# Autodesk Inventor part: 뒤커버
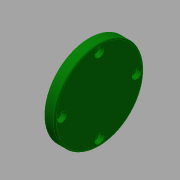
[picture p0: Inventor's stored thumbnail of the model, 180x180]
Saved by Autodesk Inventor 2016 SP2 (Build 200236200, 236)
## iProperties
Created: 2015-09
Part Number: 뒤커버
Material: 알루미늄 6061
Document SubType Name: Modeling
Designer: mduedu
Density: 2.71 g/cm^3
Mass: 54.0417 g
Surface Area: 84.9688 cm^2
Volume: 19.9416 cm^3
Appearance: 진녹색
Author: mduedu
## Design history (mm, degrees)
sketch "스케치1"
  geometry: L1 (-15.5, 47)-(-15.5, 78); L2 (-15.5, 78)-(-22.5, 78); L3 (-22.5, 78)-(-22.5, 63); L4 (-28.5, 63)-(-28.5, 47); L5 (-79.5, 39.5)-(-79.5, 54.5) reference; L6 (48.5, 54.5)-(48.5, 39.5) reference; L7 (-79.5, 47)-(48.5, 47); L8 (-22.5, 63)-(-28.5, 63); L9 (-28.5, 47)-(-15.5, 47); 1 further point
  constraints: 14 end point, 4 midpoint, 3 parallel, 1 collinear, 1 point on line, 1 vertical
  dimensions: "d6" = 62 diameter of L2 L7; "d7" = 7 distance of L1.end L2.end; "d8" = 32 diameter of L3.end L7; "d32" = 13 distance between parallel lines of L1 L4
revolve "회전1" sketch "스케치1" stored, may be unused: angle "d4" = 90 deg
sketch "스케치4"
  geometry: C1 r 31 at (0, 0) reference; 2 further points
  constraints: 1 coincident
hole "구멍3" sketch "스케치4" at (0, 0) diameter "d33" = 22; stored, may be unused: countersink angle "d37" = 90 deg, drill point angle "d39" = 0 deg; dims "d34" = 6, "d35" = 4, "d36" = 2, "d38" = 8
fillet "모깎기4" dims "d40" = 1
chamfer "모따기2" distance "d41" = 1; stored, may be unused: second distance "d42" = 2, angle "d43" = 45 deg
sketch "스케치6" dims "d56" = 52
  geometry: C1 r 31 at (0, 0) reference; 5 further points
  constraints: 2 vertical alignment, 1 coincident, 7 other
  dimensions: "d59" = 360 deg dimension on C1.centre point (0, 26) (derived)
hole "구멍4" sketch "스케치6" at (0, 26), (-26, 0), (0, -26), (26, 0) diameter "d49" = 3.4; stored, may be unused: countersink angle "d53" = 90 deg, drill point angle "d55" = 0 deg; dims "d50" = 6, "d51" = 6.5, "d52" = 3.4, "d54" = 8
fillet "모깎기5" dims "d61" = 3
node "솔리드1"
node "참조1"
node "참조2"
